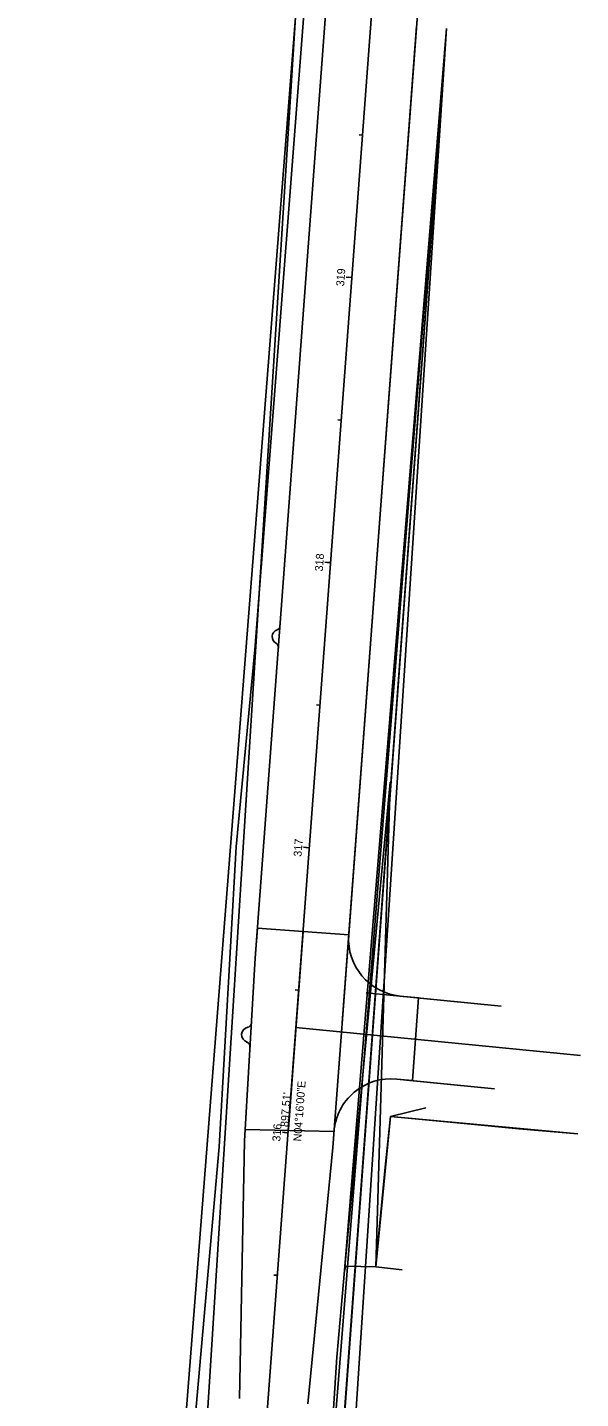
# Model space of a CAD drawing. Extents: x 219353 to 221640, y 361458 to 364236.
# Drawn here: x 220538 to 220731.4, y 362963.2 to 363442.9 of the extents above; entities that cross this region are included whole.
import ezdxf

# ---------------------------------------------------------------- set-up
doc = ezdxf.new("R2010")
doc.units = 0
for name, color, linetype in [('Default', 7, 'Continuous'), ('DR_P_Cells', 7, 'Continuous'), ('DR_P_GenericNode', 7, 'Continuous'), ('DR_X_GenericNode', 7, 'Continuous'), ('DT_X_Contour_Major', 7, 'Continuous'), ('DT_X_Contour_Minor', 7, 'Continuous'), ('DT_X_Island', 7, 'Continuous'), ('SC_ProfileRun1', 7, 'Continuous'), ('SC_ProfileRun3', 7, 'Continuous'), ('SC_Scratch1', 7, 'Continuous'), ('UT_X_San_Storm_Line', 7, 'Continuous'), ('UT_X_Sanitary_Cells', 7, 'Continuous'), ('UT_X_Sanitary_Line', 7, 'Continuous')]:
    doc.layers.add(name, color=color, linetype=linetype)

msp = doc.modelspace()

# ---------------------------------------------------------------- linework, layer by layer
at = {"layer": 'Default'}
for p, q in [((220606.11, 362243.12), (220684.52, 363442.47)), ((220684.52, 363442.47), (220615.71, 362509.09)), ((220624.82, 362631.32), (220684.52, 363442.47)), ((220684.52, 363442.47), (220626.15, 362649.27)), ((220641.07, 362898.72), (220684.52, 363442.47)), ((220684.52, 363442.47), (220648.9, 363007.94)), ((220648.9, 363007.94), (220664.85, 363178.86)), ((220664.85, 363178.86), (220659.85, 363009.25)), ((220664.99, 363061.91), (220677.28, 363064.88)), ((220659.85, 363009.25), (220664.99, 363061.91))]:
    msp.add_line(p, q, dxfattribs=at)
at = {"layer": 'DR_X_GenericNode'}
for p, q in [((220617.63, 363117.2), (220647.21, 363513.59)), ((220617.48, 363225.17), (220639.08, 363505.31)), ((220631.67, 363446.41), (220538.01, 362247.29)), ((220541.47, 362010.88), (220631.67, 363446.41)), ((220610.96, 363156.24), (220617.48, 363225.17)), ((220605.02, 363051.24), (220610.96, 363156.24)), ((220644.78, 363051), (220650.33, 363125.39)), ((220613.87, 363053.31), (220617.63, 363117.2)), ((220664.99, 363061.91), (220677.28, 363064.88)), ((220659.85, 363009.25), (220664.99, 363061.91)), ((220575.71, 362719.33), (220605.02, 363051.24)), ((220612.16, 362963.18), (220613.87, 363053.31)), ((220636.09, 362961.4), (220644.78, 363051)), ((220646.21, 362977.69), (220648.9, 363007.94)), ((220648.9, 363007.94), (220649.3, 363009.55)), ((220649.3, 363009.55), (220659.85, 363009.25)), ((220641.07, 362898.72), (220646.21, 362977.69))]:
    msp.add_line(p, q, dxfattribs=at)
at = {"layer": 'DT_X_Contour_Major'}
for p, q in [((220596.38, 362617.24), (220663.15, 363512.27)), ((220631.87, 363093.04), (220731.39, 363083.18))]:
    msp.add_line(p, q, dxfattribs=at)
at = {"layer": 'DT_X_Contour_Minor'}
for p, q in [((220617.63, 363117.2), (220647.21, 363513.59)), ((220617.63, 363117.2), (220647.21, 363513.59)), ((220648.04, 363094.66), (220676, 363469.4)), ((220650.33, 363125.39), (220674.05, 363443.25)), ((220618.42, 363127.77), (220650.33, 363125.39)), ((220629.23, 363057.59), (220634.38, 363126.58)), ((220644.78, 363051), (220650.33, 363125.39)), ((220644.78, 363051), (220650.33, 363125.39)), ((220613.87, 363053.31), (220617.63, 363117.2)), ((220613.87, 363053.31), (220617.63, 363117.2)), ((220656.47, 363105.17), (220703.6, 363100.5)), ((220668.3, 363104), (220703.6, 363100.5)), ((220668.3, 363104), (220703.6, 363100.5)), ((220667.12, 363074.98), (220701.27, 363071.59)), ((220667.12, 363074.98), (220701.27, 363071.59)), ((220670.59, 363074.63), (220701.27, 363071.59)), ((220659.85, 363009.25), (220664.99, 363061.91)), ((220664.99, 363061.91), (220730.48, 363055.77)), ((220614.1, 363057.3), (220645.2, 363056.56)), ((220612.16, 362963.18), (220613.87, 363053.31)), ((220612.16, 362963.18), (220613.87, 363053.31)), ((220636.09, 362961.4), (220644.78, 363051)), ((220636.09, 362961.4), (220644.78, 363051)), ((220669.05, 363008.23), (220659.85, 363009.25))]:
    msp.add_line(p, q, dxfattribs=at)
for centre, start, end in [((220670.28, 363123.9), 175.7333, 264.3384), ((220670.28, 363123.9), 175.7333, 264.3384), ((220665.14, 363055.07), 84.3384, 175.7333), ((220665.14, 363055.07), 84.3384, 175.7333)]:
    msp.add_arc(centre, 20, start, end, dxfattribs=at)
at = {"layer": 'DT_X_Island'}
for p, q in [((220626.3, 363233.43), (220626.38, 363234.4)), ((220625.72, 363225.55), (220625.75, 363225.96)), ((220616.3, 363094.48), (220616.3, 363094.58)), ((220615.77, 363085.64), (220615.82, 363086.38))]:
    msp.add_line(p, q, dxfattribs=at)
msp.add_lwpolyline([(220730.48, 363055.77), (220709.84, 363057.53), (220690.73, 363059.46), (220664.99, 363061.91), (220663.09, 363044.16), (220660.99, 363022.18), (220659.85, 363009.25), (220669.05, 363008.23)], dxfattribs=at)
for centre, radius, start, end in [((220626.15, 363229.69), 2.58, 109.166, 242.3006), ((220624.81, 363233.54), 1.5, 289.166, 355.7333), ((220624.25, 363226.07), 1.5, 355.7333, 62.3006), ((220615.58, 363090.46), 2.68, 100.739, 252.5179), ((220614.8, 363094.57), 1.5, 280.739, 356.6284), ((220614.32, 363086.47), 1.5, 356.6284, 72.5179)]:
    msp.add_arc(centre, radius, start, end, dxfattribs=at)
at = {"layer": 'SC_ProfileRun3'}
for p, q in [((220651.45, 363355.35), (220650.25, 363355.44)), ((220644.01, 363255.63), (220642.81, 363255.71)), ((220636.57, 363155.9), (220635.37, 363155.99)), ((220629.13, 363056.18), (220627.93, 363056.27))]:
    msp.add_line(p, q, dxfattribs=at)
at = {"layer": 'UT_X_San_Storm_Line'}
for p, q in [((220617.63, 363117.2), (220618.42, 363127.77)), ((220614.1, 363057.3), (220617.63, 363117.2)), ((220668.3, 363104), (220674.76, 363103.36)), ((220667.12, 363074.98), (220672.6, 363074.43))]:
    msp.add_line(p, q, dxfattribs=at)
for centre, start, end in [((220670.28, 363123.9), 175.7333, 264.3384), ((220665.14, 363055.07), 84.3384, 175.7333)]:
    msp.add_arc(centre, 20, start, end, dxfattribs=at)
at = {"layer": 'UT_X_Sanitary_Cells'}
for p, q in [((220655.17, 363405.21), (220653.97, 363405.3)), ((220651.45, 363355.35), (220649.45, 363355.5)), ((220647.73, 363305.49), (220646.53, 363305.58)), ((220644.01, 363255.63), (220642.01, 363255.77)), ((220640.29, 363205.76), (220639.09, 363205.85)), ((220636.57, 363155.9), (220634.57, 363156.05)), ((220632.85, 363106.04), (220631.65, 363106.13)), ((220629.13, 363056.18), (220627.13, 363056.33)), ((220625.41, 363006.32), (220624.21, 363006.41))]:
    msp.add_line(p, q, dxfattribs=at)
at = {"layer": 'UT_X_Sanitary_Line'}
msp.add_line((220672.6, 363074.43), (220674.76, 363103.36), dxfattribs=at)

# ---------------------------------------------------------------- texts
at = {"layer": 'DR_P_Cells'}
msp.add_text("897.51'", height=2.8, rotation=85.7333, dxfattribs=at).set_placement((220629.23, 363058.1))
at = {"layer": 'DR_P_GenericNode'}
msp.add_text("897.51'", height=2.8, rotation=85.7333, dxfattribs=at).set_placement((220629.23, 363058.1))
at = {"layer": 'SC_ProfileRun1'}
msp.add_text('N04°16\'00"E', height=2.8, rotation=85.7333, dxfattribs=at).set_placement((220633.71, 363053.07))
at = {"layer": 'SC_Scratch1'}
msp.add_text('N04°16\'00"E', height=2.8, rotation=85.7333, dxfattribs=at).set_placement((220633.71, 363053.07))
at = {"layer": 'UT_X_Sanitary_Cells'}
for s, p in [('319', (220648.71, 363352.22)), ('318', (220641.26, 363252.49)), ('317', (220633.82, 363152.68)), ('316', (220626.38, 363053.02))]:
    msp.add_text(s, height=2.8, rotation=85.7333, dxfattribs=at).set_placement(p)

doc.saveas('drawing.dxf')
